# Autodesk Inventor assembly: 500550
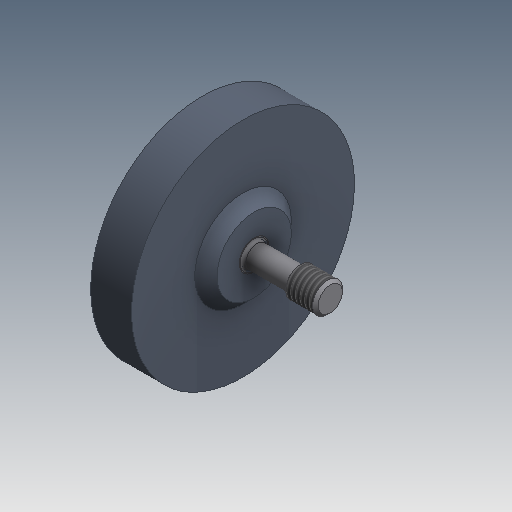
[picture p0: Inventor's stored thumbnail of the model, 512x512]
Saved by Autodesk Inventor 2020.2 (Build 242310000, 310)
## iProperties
Created: 2000-02
Part Number: 500550
Document SubType Name: Assembly
Designer: dmcquary
Mass: 54.8212 g
Surface Area: 90.7551 cm^2
Volume: 40.5054 cm^3
Density: 1.35343 g/cm^3
Control State: 0
Checked Out: False
Master: False
Shininess: 0.0
Length Units: 11272
Angle Units: 11279
Time Units: 11290
Mass Units: 11286
Length Display Precision: 3
Angle Display Precision: 2
Compacted: True
Dimensions: 2,4x2,4x1,6 in
Mass: 0,121 lb
DocNumber: 500550.iam
Folder: 01 - Themengebiete\Simplification\01 - Packaging machine\
VDS_Category: 3D Komponenten
Density: 0.0
Volumn: 0.0
Area: 0.0
PropertySet Name: Model Information
Author: dmcquary
Revision Number: -
Title: 500550
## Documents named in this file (3)
- D:\07 - DEMODATEN\OTX 2019 - Dataset - UPDATE - Dez2019\Designs\07-Packing machine\500550.iam
- D:\07 - DEMODATEN\OTX 2019 - Dataset - UPDATE - Dez2019\Designs\07-Packing machine\Parts\ADSK-011771.ipt
- D:\07 - DEMODATEN\OTX 2019 - Dataset - UPDATE - Dez2019\Designs\07-Packing machine\Parts\ADSK-011490.ipt
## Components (2 placed, 2 different names)
1. ADSK-011771:1 — Einfügen:1
2. ADSK-011490:1 — Einfügen:1
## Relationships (1: Insert 1)
- Einfügen:1 [Insert]: ADSK-011771:1 ↔ ADSK-011490:1
